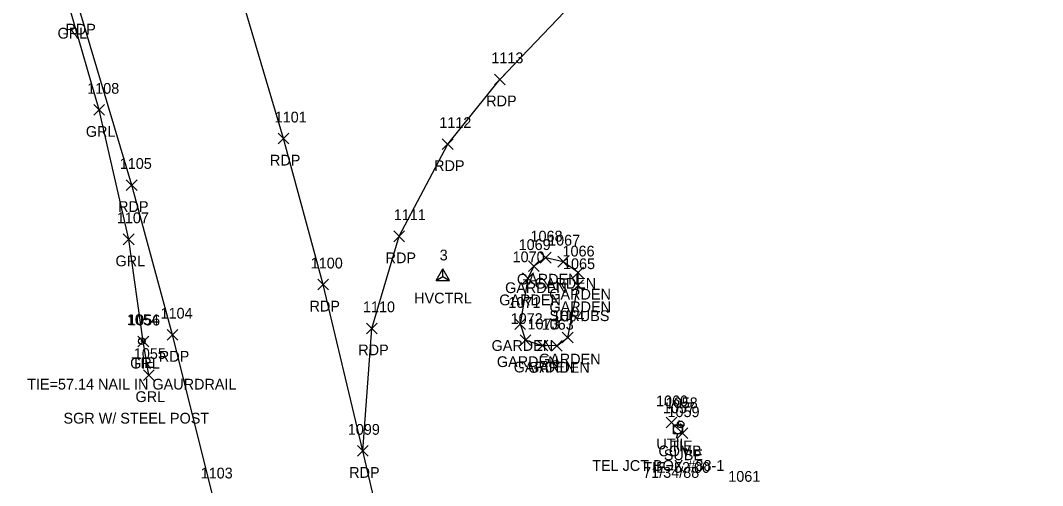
# Model space of a CAD drawing. Extents: x 1496556 to 1498241, y 599216 to 604470.
# Drawn here: x 1497213.5 to 1497403.3, y 602926.1 to 603012.5 of the extents above; entities that cross this region are included whole.
import ezdxf

# ---------------------------------------------------------------- set-up
doc = ezdxf.new("R2010")
doc.units = 0
for name, color, linetype in [('C_A', 7, 'Continuous'), ('C_C', 7, 'Continuous'), ('C_I', 7, 'Continuous'), ('CBP', 7, 'Continuous'), ('CPSM', 7, 'Continuous'), ('L_A', 7, 'Continuous'), ('L_C', 7, 'Continuous'), ('L_I', 7, 'Continuous'), ('L_TIC', 7, 'Continuous'), ('LAPB', 7, 'Continuous'), ('P_A', 7, 'Continuous'), ('P_I', 7, 'Continuous'), ('P_TIC', 7, 'Continuous'), ('PET', 7, 'Continuous'), ('R_A', 7, 'Continuous'), ('R_C', 7, 'Continuous'), ('R_I', 7, 'Continuous'), ('R_TIC', 7, 'Continuous'), ('RGR', 7, 'Continuous'), ('U_A', 7, 'Continuous'), ('U_C', 7, 'Continuous'), ('U_I', 7, 'Continuous'), ('U_TIC', 7, 'Continuous'), ('UDEFAULT', 7, 'Continuous'), ('UP', 7, 'Continuous')]:
    doc.layers.add(name, color=color, linetype=linetype)

msp = doc.modelspace()

# ---------------------------------------------------------------- linework, layer by layer
at = {"layer": 'CBP'}
for centre, radius in [((1497236.06, 602952.91), 0.625), ((1497236.06, 602952.91), 0.0833), ((1497336.08, 602937.44), 0.625), ((1497336.08, 602937.44), 0.0833)]:
    msp.add_circle(centre, radius, dxfattribs=at)
at = {"layer": 'CPSM'}
for p, q in [((1497290.68, 602964.17), (1497291.93, 602966.34)), ((1497290.68, 602964.17), (1497291.93, 602964.9)), ((1497293.18, 602964.17), (1497291.93, 602966.34)), ((1497291.93, 602964.9), (1497291.93, 602966.34)), ((1497291.93, 602964.9), (1497291.93, 602964.9)), ((1497291.93, 602964.9), (1497293.18, 602964.17)), ((1497290.68, 602964.17), (1497293.18, 602964.17))]:
    msp.add_line(p, q, dxfattribs=at)
at = {"layer": 'L_TIC'}
for points in [[(1497310.04, 602967.41), (1497312.04, 602969.41)], [(1497312.04, 602967.41), (1497310.04, 602969.41)], [(1497313.3, 602966.66), (1497315.3, 602968.66)], [(1497315.3, 602966.66), (1497313.3, 602968.66)], [(1497307.83, 602965.83), (1497309.83, 602967.83)], [(1497309.83, 602965.83), (1497307.83, 602967.83)], [(1497316.04, 602964.63), (1497318.04, 602966.63)], [(1497318.04, 602964.63), (1497316.04, 602966.63)], [(1497306.75, 602963.57), (1497308.75, 602965.57)], [(1497308.75, 602963.57), (1497306.75, 602965.57)], [(1497316.06, 602962.28), (1497318.06, 602964.28)], [(1497318.06, 602962.28), (1497316.06, 602964.28)], [(1497305.32, 602955.09), (1497307.32, 602957.09)], [(1497307.32, 602955.09), (1497305.32, 602957.09)], [(1497306.31, 602952.09), (1497308.31, 602954.09)], [(1497308.31, 602952.09), (1497306.31, 602954.09)], [(1497314.12, 602952.57), (1497316.12, 602954.57)], [(1497316.12, 602952.57), (1497314.12, 602954.57)], [(1497309.43, 602951.09), (1497311.43, 602953.09)], [(1497311.43, 602951.09), (1497309.43, 602953.09)], [(1497309.43, 602951.09), (1497311.43, 602953.09)], [(1497311.43, 602951.09), (1497309.43, 602953.09)], [(1497312.11, 602951.03), (1497314.11, 602953.03)], [(1497314.11, 602951.03), (1497312.11, 602953.03)], [(1497312.11, 602951.03), (1497314.11, 602953.03)], [(1497314.11, 602951.03), (1497312.11, 602953.03)]]:
    msp.add_lwpolyline(points, dxfattribs=at)
at = {"layer": 'LAPB'}
for points in [[(1497313.11, 602952.03), (1497315.12, 602953.57), (1497317.06, 602963.28), (1497317.04, 602965.63), (1497314.3, 602967.66), (1497311.04, 602968.41), (1497308.83, 602966.83), (1497307.75, 602964.57), (1497306.32, 602956.09), (1497307.31, 602953.09), (1497310.43, 602952.09)], [(1497313.11, 602952.03), (1497310.43, 602952.09)]]:
    msp.add_lwpolyline(points, dxfattribs=at)
at = {"layer": 'P_TIC'}
for points in [[(1497301.51, 603000.53), (1497303.51, 603002.53)], [(1497303.51, 603000.53), (1497301.51, 603002.53)], [(1497261.37, 602989.53), (1497263.37, 602991.53)], [(1497263.37, 602989.53), (1497261.37, 602991.53)], [(1497291.85, 602988.5), (1497293.85, 602990.5)], [(1497293.85, 602988.5), (1497291.85, 602990.5)], [(1497233.18, 602980.9), (1497235.18, 602982.9)], [(1497235.18, 602980.9), (1497233.18, 602982.9)], [(1497282.83, 602971.38), (1497284.83, 602973.38)], [(1497284.83, 602971.38), (1497282.83, 602973.38)], [(1497268.71, 602962.41), (1497270.71, 602964.41)], [(1497270.71, 602962.41), (1497268.71, 602964.41)], [(1497277.76, 602954.27), (1497279.76, 602956.27)], [(1497279.76, 602954.27), (1497277.76, 602956.27)], [(1497240.75, 602953.09), (1497242.75, 602955.09)], [(1497242.75, 602953.09), (1497240.75, 602955.09)], [(1497276.08, 602931.51), (1497278.08, 602933.51)], [(1497278.08, 602931.51), (1497276.08, 602933.51)], [(1497276.08, 602931.51), (1497278.08, 602933.51)], [(1497278.08, 602931.51), (1497276.08, 602933.51)]]:
    msp.add_lwpolyline(points, dxfattribs=at)
at = {"layer": 'PET'}
for points in [[(1497277.08, 602932.51), (1497278.76, 602955.27), (1497283.83, 602972.38), (1497292.85, 602989.5), (1497302.51, 603001.53), (1497319.84, 603019.72), (1497338.13, 603037.05), (1497360.02, 603057.19), (1497386.8, 603081.38), (1497411.61, 603104.29), (1497436.99, 603126.72), (1497459.34, 603147.15), (1497493.2, 603178.11), (1497522.29, 603204.31), (1497552.95, 603231.97)], [(1497283.12, 602906.81), (1497277.08, 602932.51), (1497269.71, 602963.41), (1497262.37, 602990.53), (1497251.88, 603025.88), (1497245.34, 603044.47), (1497231.7, 603087.32), (1497213.53, 603046.79)], [(1497255.35, 601840.33), (1497260.72, 601945.51), (1497260.6, 601945.5), (1497265.21, 602060.91), (1497267.76, 602124.12), (1497271.3, 602209.29), (1497274.95, 602307.82), (1497276.81, 602364.31), (1497278.84, 602406.87), (1497280.41, 602449.54), (1497282.45, 602505.14), (1497283.29, 602549.03), (1497283.31, 602599.78), (1497282.4, 602667.07), (1497280.87, 602701.36), (1497277.35, 602744.02), (1497266.99, 602833.93), (1497261.25, 602868.44), (1497249.2, 602924.4), (1497241.75, 602954.09), (1497234.18, 602981.9), (1497224.39, 603014.86), (1497221.77, 603020.8), (1497213.53, 603046.79)]]:
    msp.add_lwpolyline(points, dxfattribs=at)
at = {"layer": 'R_TIC'}
for points in [[(1497227.13, 602994.86), (1497229.13, 602996.86)], [(1497229.13, 602994.86), (1497227.13, 602996.86)], [(1497232.63, 602970.81), (1497234.63, 602972.81)], [(1497234.63, 602970.81), (1497232.63, 602972.81)], [(1497235.34, 602951.82), (1497237.34, 602953.82)], [(1497237.34, 602951.82), (1497235.34, 602953.82)], [(1497236.35, 602945.59), (1497238.35, 602947.59)], [(1497238.35, 602945.59), (1497236.35, 602947.59)]]:
    msp.add_lwpolyline(points, dxfattribs=at)
at = {"layer": 'RGR'}
msp.add_lwpolyline([(1497237.35, 602946.59), (1497236.34, 602952.82), (1497233.63, 602971.81), (1497228.13, 602995.86), (1497222.87, 603014.11), (1497220.92, 603020.52), (1497213.91, 603044.59)], dxfattribs=at)
at = {"layer": 'U_TIC'}
for points in [[(1497335.43, 602934.79), (1497337.43, 602936.79)], [(1497337.43, 602934.79), (1497335.43, 602936.79)]]:
    msp.add_lwpolyline(points, dxfattribs=at)
at = {"layer": 'UDEFAULT'}
for points in [[(1497333.41, 602936.8), (1497335.41, 602938.8)], [(1497335.41, 602936.8), (1497333.41, 602938.8)]]:
    msp.add_lwpolyline(points, dxfattribs=at)
at = {"layer": 'UP'}
for p, q in [((1497335.82, 602938.18), (1497335.57, 602937.35)), ((1497334.74, 602935.68), (1497334.74, 602937.35)), ((1497334.74, 602937.35), (1497336.41, 602937.35)), ((1497335.57, 602936.51), (1497335.57, 602936.51)), ((1497336.41, 602937.35), (1497336.41, 602935.68)), ((1497336.41, 602935.68), (1497334.74, 602935.68)), ((1497335.32, 602934.85), (1497335.57, 602935.68))]:
    msp.add_line(p, q, dxfattribs=at)
msp.add_circle((1497335.57, 602936.51), 0.833, dxfattribs=at)

# ---------------------------------------------------------------- texts
at = {"layer": 'C_A'}
for s, p in [('HVCTRL', (1497286.62, 602959.9)), ('TIE', (1497234.14, 602947.91)), ('TIE', (1497334.16, 602932.44))]:
    msp.add_text(s, height=2, dxfattribs=at).set_placement(p)
at = {"layer": 'C_C'}
for s, p in [('TIE=57.14 NAIL IN GAURDRAIL', (1497214.77, 602943.91)), ('TIE=52.00', (1497329.14, 602928.44))]:
    msp.add_text(s, height=2, dxfattribs=at).set_placement(p)
at = {"layer": 'C_I'}
for s, p in [('3', (1497291.36, 602967.9)), ('1054', (1497233.29, 602955.91)), ('1058', (1497333.31, 602940.44))]:
    msp.add_text(s, height=2, dxfattribs=at).set_placement(p)
at = {"layer": 'L_A'}
for p in [(1497305.7, 602963.41), (1497303.5, 602961.83), (1497308.97, 602962.66), (1497302.42, 602959.57), (1497311.71, 602960.63), (1497311.73, 602958.28), (1497300.99, 602951.09), (1497301.98, 602948.09), (1497309.79, 602948.57), (1497305.1, 602947.09), (1497305.1, 602947.09), (1497307.78, 602947.03), (1497307.78, 602947.03)]:
    msp.add_text('GARDEN', height=2, dxfattribs=at).set_placement(p)
at = {"layer": 'L_C'}
msp.add_text('SHRUBS', height=2, dxfattribs=at).set_placement((1497311.73, 602956.63))
at = {"layer": 'L_I'}
for s, p in [('1068', (1497308.22, 602971.41)), ('1067', (1497311.48, 602970.66)), ('1069', (1497306.01, 602969.83)), ('1066', (1497314.16, 602968.63)), ('1070', (1497304.89, 602967.57)), ('1065', (1497314.25, 602966.28)), ('1071', (1497304.11, 602959.09)), ('1072', (1497304.53, 602956.09)), ('1073', (1497307.66, 602955.09)), ('1073', (1497307.66, 602955.09)), ('1064', (1497312.3, 602956.57)), ('1063', (1497310.29, 602955.03)), ('1063', (1497310.29, 602955.03))]:
    msp.add_text(s, height=2, dxfattribs=at).set_placement(p)
at = {"layer": 'P_A'}
for p in [(1497221.88, 603009.86), (1497300, 602996.53), (1497259.85, 602985.53), (1497290.33, 602984.5), (1497231.67, 602976.9), (1497281.32, 602967.38), (1497267.2, 602958.41), (1497276.25, 602950.27), (1497239.23, 602949.09), (1497274.56, 602927.51), (1497274.56, 602927.51)]:
    msp.add_text('RDP', height=2, dxfattribs=at).set_placement(p)
at = {"layer": 'P_I'}
for s, p in [('1113', (1497300.95, 603004.53)), ('1101', (1497260.73, 602993.53)), ('1112', (1497291.29, 602992.5)), ('1105', (1497231.97, 602984.9)), ('1111', (1497282.84, 602975.38)), ('1100', (1497267.42, 602966.41)), ('1104', (1497239.54, 602957.09)), ('1110', (1497277.11, 602958.27)), ('1099', (1497274.3, 602935.51)), ('1099', (1497274.3, 602935.51)), ('1103', (1497246.99, 602927.4))]:
    msp.add_text(s, height=2, dxfattribs=at).set_placement(p)
at = {"layer": 'R_A'}
for p in [(1497220.42, 603009.11), (1497225.67, 602990.86), (1497231.18, 602966.81), (1497233.89, 602947.82), (1497234.89, 602941.59)]:
    msp.add_text('GRL', height=2, dxfattribs=at).set_placement(p)
at = {"layer": 'R_C'}
msp.add_text('SGR W/ STEEL POST', height=2, dxfattribs=at).set_placement((1497221.52, 602937.59))
at = {"layer": 'R_I'}
for s, p in [('1108', (1497225.92, 602998.86)), ('1107', (1497231.43, 602974.81)), ('1056', (1497233.52, 602955.82)), ('1055', (1497234.58, 602949.59))]:
    msp.add_text(s, height=2, dxfattribs=at).set_placement(p)
at = {"layer": 'U_A'}
for s, p in [('UTIL', (1497331.58, 602932.8)), ('COMB', (1497331.96, 602931.51)), ('SUBE', (1497332.96, 602930.79))]:
    msp.add_text(s, height=2, dxfattribs=at).set_placement(p)
at = {"layer": 'U_C'}
for s, p in [('TEL JCT BOX #88-1', (1497319.67, 602928.8)), ('71/34/88', (1497329.13, 602927.51))]:
    msp.add_text(s, height=2, dxfattribs=at).set_placement(p)
at = {"layer": 'U_I'}
for s, p in [('1060', (1497331.51, 602940.8)), ('1057', (1497332.8, 602939.51)), ('1059', (1497333.65, 602938.79)), ('1061', (1497344.93, 602926.78))]:
    msp.add_text(s, height=2, dxfattribs=at).set_placement(p)

doc.saveas('drawing.dxf')
